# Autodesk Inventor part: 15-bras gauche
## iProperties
Created: 2011-02
Part Number: 15-bras gauche
Document SubType Name: Modeling
Designer: eric
Density: 1 g/cm^3
Author: eric
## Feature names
1. Base1
